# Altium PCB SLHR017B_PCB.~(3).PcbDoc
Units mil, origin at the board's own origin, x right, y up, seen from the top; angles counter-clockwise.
Board outline 3125 x 2100 mil, 2 copper layers (Top Layer, Bottom Layer), stack 61.2 mil thick; 59 components, 16 nets, 85 pads, 115 vias.
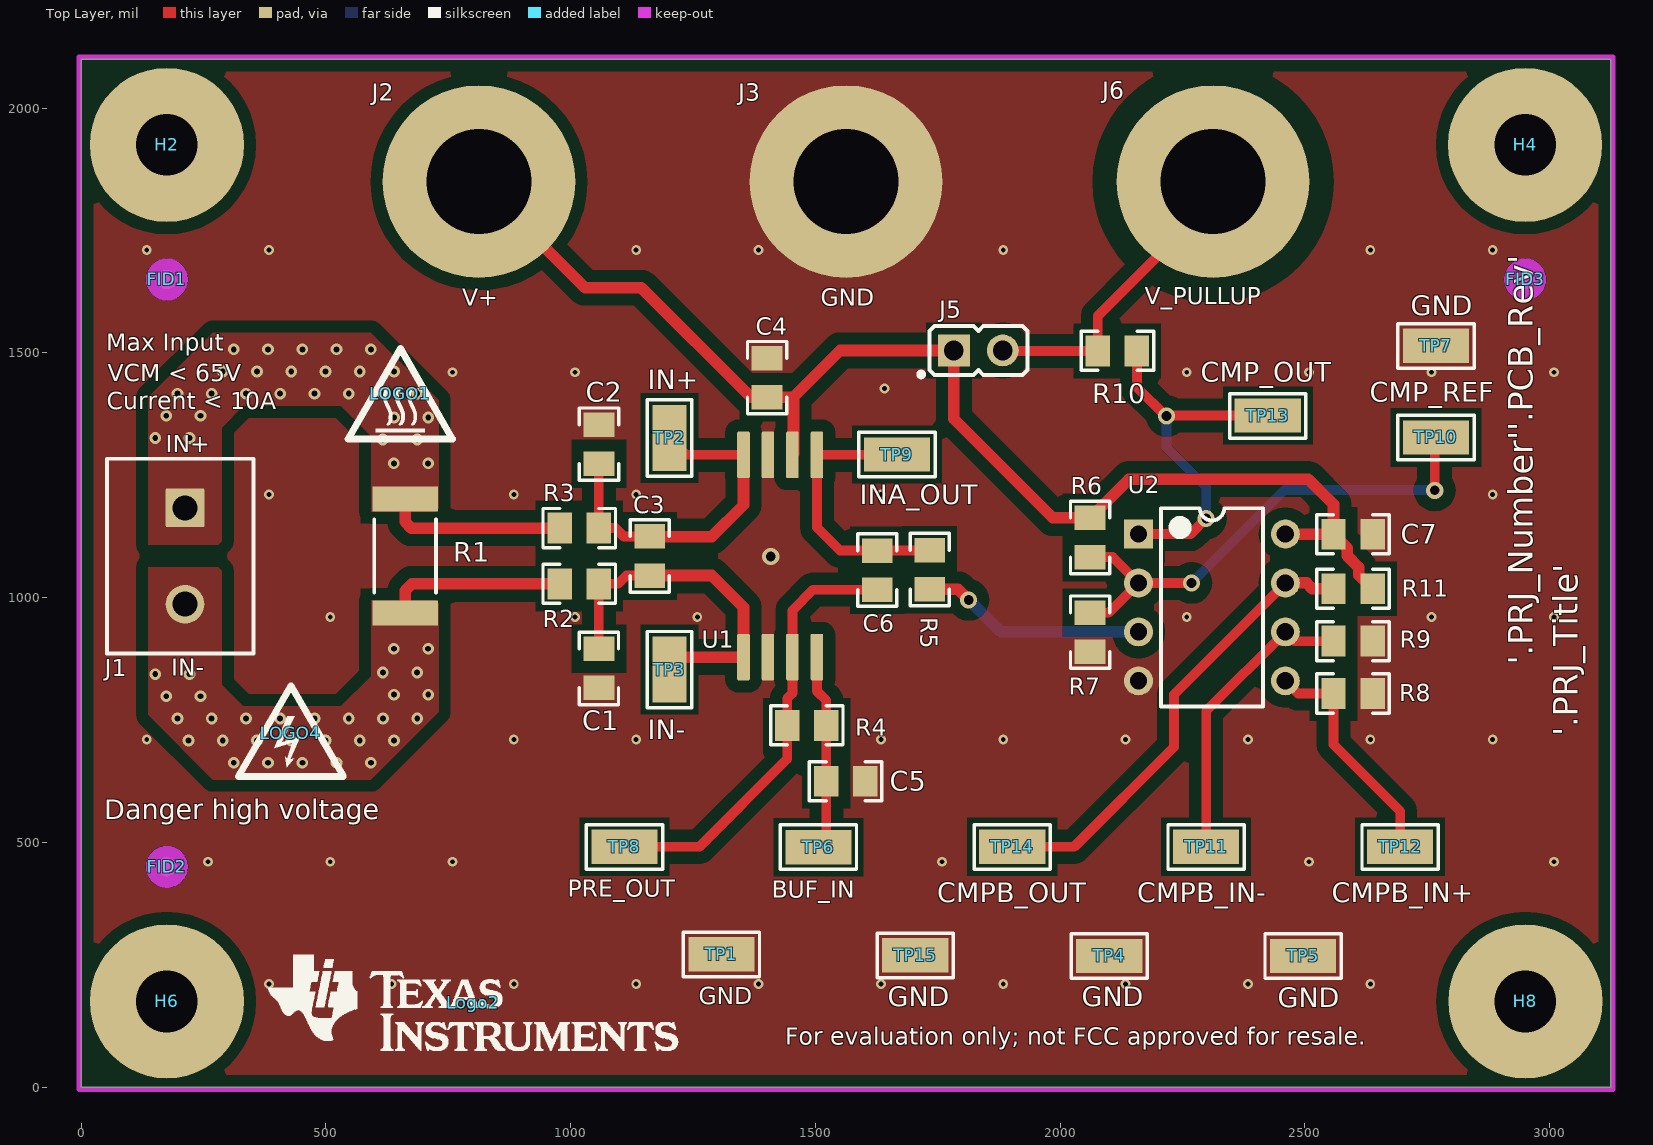
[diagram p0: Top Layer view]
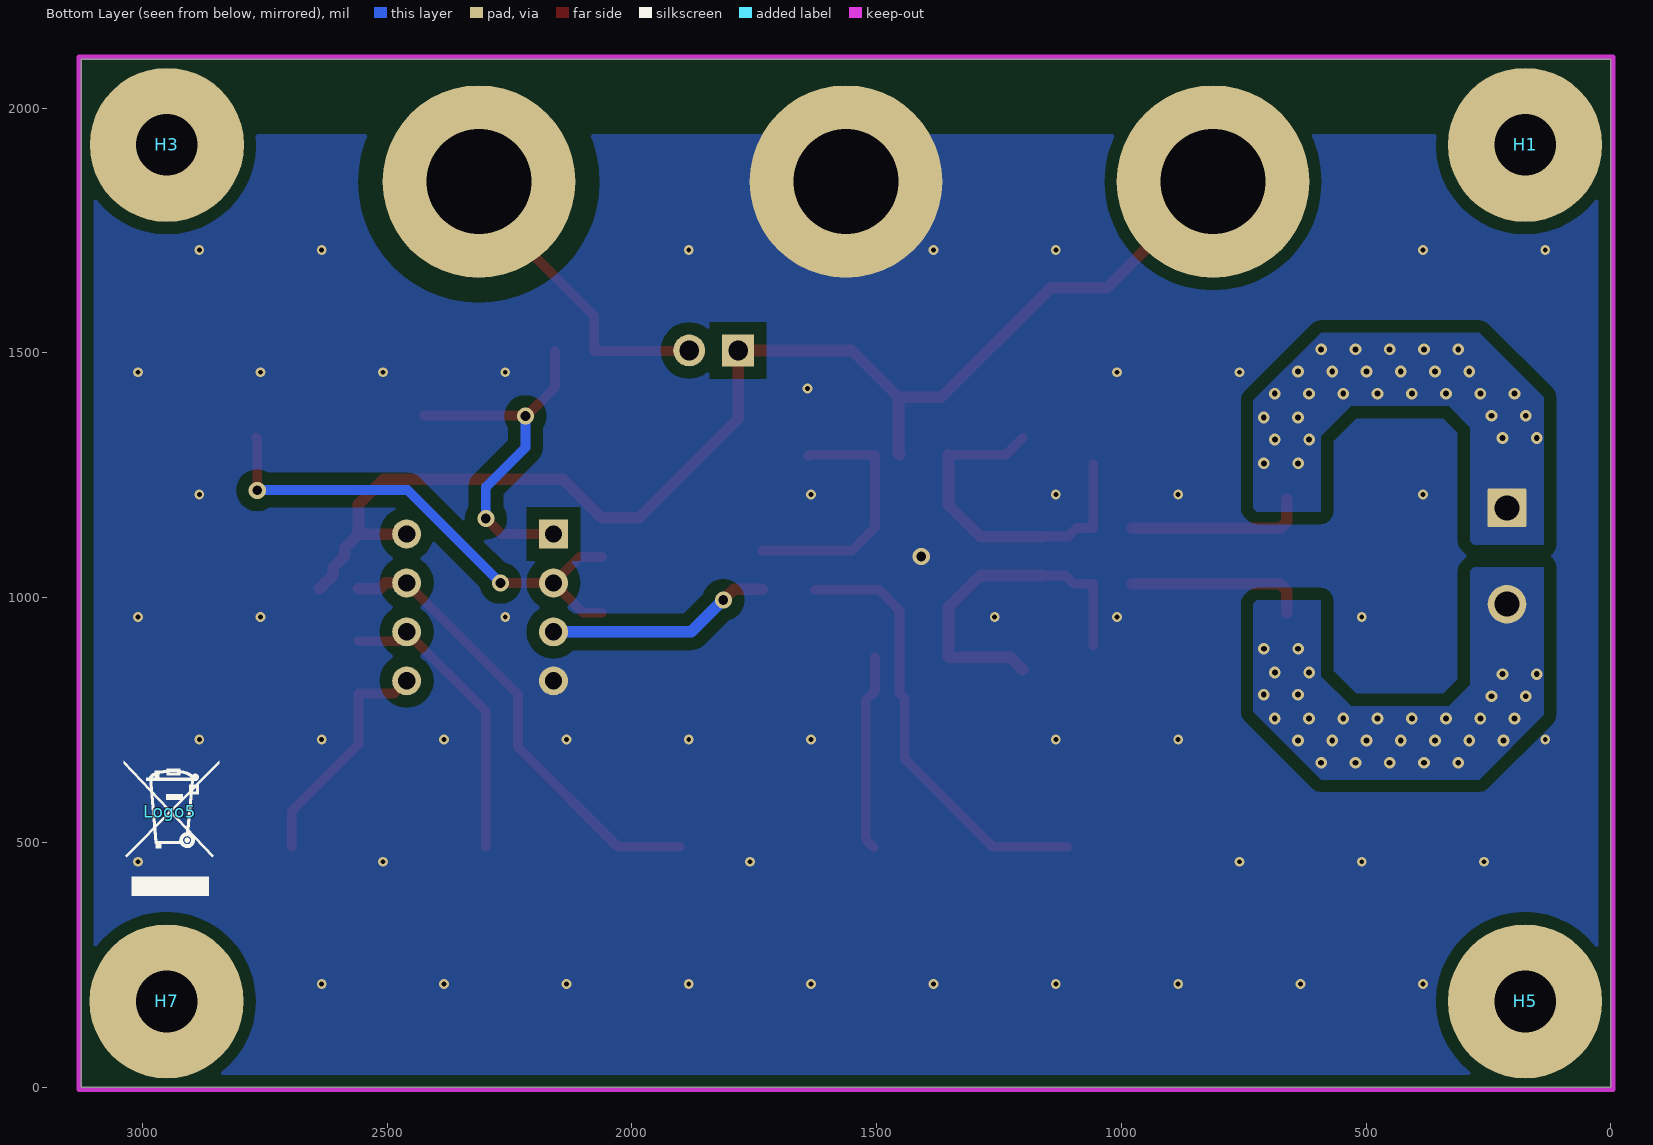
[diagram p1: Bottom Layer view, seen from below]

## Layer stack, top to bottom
Top Solder: solder mask 0.4, Solder Resist, Dk 3.5
Top Layer: signal copper 2.1
Dielectric1: core 57, FR-4 High Tg, Dk 4.8
Bottom Layer: signal copper 2.1
Bottom Solder: solder mask 0.4, Solder Resist, Dk 3.5

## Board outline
0,0 3125,0 3125,2100 0,2100
cut-out: -1616.23,-2039.56 -1606.23,-2039.56 -1606.23,-2029.56 -1616.23,-2029.56

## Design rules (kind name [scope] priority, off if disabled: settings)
AcuteAngle [All] p1: minimum=4.50000000000000E+0001 checktracksonly=FALSE
AssemblyTestPointUsage [All] p1: valid=2
Clearance Clearance_HV [InNetClass('HV_Net')] p1: gap=25 ignorepadtopadclearanceinfootprint=TRUE except(50: THPad-Poly Poly-Poly)
Clearance Clearance_Keepouts [((IsTrack Or IsArc) And Not InPoly) And IsFree and IsKeepOut vs ((IsTrack Or IsArc) And Not InPoly) And IsFree and IsKeepOut] p2: gap=0 ignorepadtopadclearanceinfootprint=FALSE
Clearance Clearance_Fiducial [InComponentClass('FiducialMark')] p3: gap=0 ignorepadtopadclearanceinfootprint=FALSE
Clearance Clearance_BoardEdge_MountingHoles [OnCopper and InComponentClass('Mounting Holes') vs IsKeepOut] p4: gap=40 ignorepadtopadclearanceinfootprint=FALSE except(15: Track-THPad)
Clearance Clearance_BoardEdge_Poly [OnCopper and InPoly vs IsKeepOut] p5: gap=25 ignorepadtopadclearanceinfootprint=FALSE
Clearance Clearance_Jack_Poly [InPolygon vs InPadClass('Jack')] p6: gap=25 ignorepadtopadclearanceinfootprint=FALSE except(50: Arc-Poly Track-Poly SMDPad-Poly THPad-Poly Via-Poly Fill-Poly Poly-Poly)
Clearance Clearance_Poly [InPolygon] p7: gap=25 ignorepadtopadclearanceinfootprint=FALSE
Clearance [All] p8: gap=15 ignorepadtopadclearanceinfootprint=FALSE
ComponentClearance ComponentClearance_MountingHoles_FiducialMarks [InComponentClass('Mounting Holes') vs InComponentClass('FiducialMark')] p1: gap=50 collisioncheckmode=3 verticalgap=10 showdistances=FALSE
ComponentClearance ComponentClearance_Logo [InComponentClass('Logo')] p2: gap=50 collisioncheckmode=3 verticalgap=100000 showdistances=FALSE
ComponentClearance ComponentClearance_ScrewToNut [(HasFootprint('NY PMS 440 0025 PH')) vs (HasFootprint('Keystone_1902C'))] p3: gap=0 collisioncheckmode=3 verticalgap=0 showdistances=FALSE
ComponentClearance ComponentClearance_MountingHoles [InComponentClass('Mounting Holes')] p4: gap=30 collisioncheckmode=3 verticalgap=100000 showdistances=FALSE
ComponentClearance [All] p5: gap=20 collisioncheckmode=3 verticalgap=10 showdistances=FALSE
DiffPairsRouting [All] p1: maxlimit=100 minlimit=10 mostfreqgap=10 toplayer_minwidth=15 toplayer_maxwidth=15 toplayer_prefwidth=15 bottomlayer_minwidth=15 bottomlayer_maxwidth=15 bottomlayer_prefwidth=15 maxuncoupledlength=1000
FabricationTestPointUsage TestPointUsage [All] p1: valid=2 allowmultiple=FALSE
FabricationTestpoint Testpoint [All] p1: side=3 testpointundercomponent=TRUE minsize=40 maxsize=100 preferedsize=60 minholesize=0 maxholesize=40 preferedholesize=32 testpointgrid=1 allowsidetop=TRUE allowsidebottom=TRUE usegrid=TRUE gridtolerance=0.01
FanoutControl Fanout_LCC [IsLCC] p1: bgadir=Out bgaviamode=Centered fanoutstyle=Auto fanoutdirection=Alternating viagrid=1 // Fanout_LCC (Default Rule)
FanoutControl Fanout_BGA [IsBGA] p2: bgadir=Out bgaviamode=Centered fanoutstyle=Auto fanoutdirection=Alternating viagrid=1 // Fanout_BGA (Default Rule)
FanoutControl Fanout_Default [All] p4: bgadir=Out bgaviamode=Centered fanoutstyle=Auto fanoutdirection=Alternating viagrid=1 // Fanout_Default (Default Rule)
FanoutControl Fanout_Small [(CompPinCount < 5)] p5: bgadir=Out bgaviamode=Centered fanoutstyle=Auto fanoutdirection=OutThenIn viagrid=1 // Fanout_Small (Default Rule)
HoleSize [All] p1: absolutevalues=TRUE maxlimit=251 minlimit=8 maxpercent=80.000 minpercent=20.000
MinimumAnnularRing [All] p1: minimumring=6
MinimumSolderMaskSliver MinimumSolderMaskSliver_Logo [InComponentClass('Logo') vs InComponentClass('Logo')] p1: minsoldermaskwidth=0.7
MinimumSolderMaskSliver [All] p2: minsoldermaskwidth=4
PlaneConnect [All] p1: planeconnectstyle=Relief reliefexpansion=10 reliefentries=4 reliefconductorwidth=10 reliefairgap=10
PolygonConnect [All] p1: connectstyle=Direct reliefconductorwidth=30 reliefentries=4 polygonreliefangle="90 Angle" airgapwidth=15
RoutingVias [All] p1: holewidth=12 width=24 viastyle="Through Hole" minholewidth=5 minwidth=5 maxholewidth=20 maxwidth=40
SilkToBoardRegionClearance [Not ((IsComment or IsDesignator) And (Hide <> 'False')) and not InRegion(1000,500,4000,800)] p1:
SilkToSilkClearance SilkToSilkClearance_Pb-FreeLogo [(HasFootprint('Pb-Free_Overlay_Medium') OR HasFootprint('Pb-Free_Overlay_Small')) vs (HasFootprint('Pb-Free_Overlay_Medium') OR HasFootprint('Pb-Free_Overlay_Small'))] p1: silktosilkclearance=0
SilkToSilkClearance [All] p2: silktosilkclearance=4
SilkToSolderMaskClearance SilkToComonentPadClearance [IsPad and InAnycomponent] p1: minsilkscreentomaskgap=5 clearancetoexposedcopper=TRUE
SilkToSolderMaskClearance "Silk to Solder Mask Opening" [All] p2: minsilkscreentomaskgap=4 clearancetoexposedcopper=FALSE
SolderMaskExpansion [All] p1: expansion=0
Width [All] p1: maxlimit=100 minlimit=6 preferedwidth=10 checkconnectedcopper=TRUE
15 further rules are at their usual default settings.

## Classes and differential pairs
component class Header: J5
component class SLHR017B_MainSheet: C1 C2 C3 C4 C5 C6 C7 C? J1 J2 J3 J5 J6 R1 R2 R3 R4 R5 R6 R7 R8 R9 R10 R11 R14 TP1 TP2 TP3 TP4 TP5 TP6 TP7 TP8 TP9 TP10 TP11 TP12 TP13 TP14 TP15 TP? U1 U2 U4
component class AssemblyNote: ZZ1 ZZ2 ZZ3
component class FiducialMark: FID1 FID2 FID3
component class SLHR017B_Hardware: FID1 FID2 FID3 H1 H2 H3 H4 H5 H6 H7 H8 LOGO1 Logo2 Logo3 LOGO4 Logo5 Logo7 ZZ1 ZZ2 ZZ3
component class Logo: Logo2
component class "Mounting Holes": H2 H4 H6 H8
pad class Jack: J4-1 J6-1 J7-1 J8-1

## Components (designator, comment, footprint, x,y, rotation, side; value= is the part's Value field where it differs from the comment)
C1 "C0805C101J1RACTU" 0805_HV 1057.62,855.52 r270 top value=100pF
C2 "C0805C101J1RACTU" 0805_HV 1057.88,1313.51 r270 top value=100pF
C3 "C0805C101J1RACTU" 0805_HV 1161.69,1085 r270 top value=100pF
C4 "C0805C104K1RACTU" 0805_HV 1401.3,1449.33 r90 top value=0.1uF
C5 "VJ0805A150JXACW1BC" 0805_HV 1561.84,624.8 r0 top value=15pF
C6 "C0805C103F1GACTU" 0805_HV 1626.46,1056.19 r90 top value=0.01uF
C7 "C0805C104K1RACTU" 0805_HV 2598.57,1129.42 r0 top value=0.1uF
FID1 "Fiducial" Fiducial10-20 175,1650 r270 top locked
FID2 "Fiducial" Fiducial10-20 175,450 r0 top locked
FID3 "Fiducial" Fiducial10-20 2950,1650 r180 top locked
H1 "1902C" Keystone_1902C 175,1925 r180 bottom locked
H2 "NY PMS 440 0025 PH" "NY PMS 440 0025 PH" 175,1925 r0 top locked
H3 "1902C" Keystone_1902C 2950,1925 r180 bottom locked
H4 "NY PMS 440 0025 PH" "NY PMS 440 0025 PH" 2950,1925 r0 top locked
H5 "1902C" Keystone_1902C 175,175 r180 bottom locked
H6 "NY PMS 440 0025 PH" "NY PMS 440 0025 PH" 175,175 r0 top locked
H7 "1902C" Keystone_1902C 2950.53,175 r180 bottom locked
H8 "NY PMS 440 0025 PH" "NY PMS 440 0025 PH" 2950.53,175 r0 top locked
J1 "691137710002" FP-691137710002_HDR2-MFG 202.17,1085 r270 top
J2 "V+" Keystone_575-4 812.5,1850 r0 top
J3 "GND" Keystone_575-4 1562.5,1850 r0 top
J5 "PBC02SAAN" Sullins_PBC02SAAN 1833.04,1505 r90 top
J6 "VPULLUP" Keystone_575-4 2312.5,1850 r0 top
LOGO1 "CAUTION HOT SURFACE" IEC_HotSurface_Small 651.99,1416.8 r0 top
Logo2 "Texas Instruments" TI_Stacked_Overlay_Small 800.88,172.11 r0 top
Logo3 "FCC disclaimer" FCC_disclaimer 2122.51,-1302.18 r270 top locked
LOGO4 "DANGER HIGH VOLTAGE" IEC_HighVoltage_Small 428.39,722.78 r0 top
Logo5 "WEEE logo" WEEE_Minimum 2942.74,562.77 r180 bottom
R1 "CRA2512-FZ-R025ELF" 2512 661.64,1085 r90 top value=0.025
R2 "ERJ-6GEY0R00V" 0805_HV 1017.48,1028.16 r0 top value=0
R3 "ERJ-6GEY0R00V" 0805_HV 1017.48,1142.08 r0 top value=0
R4 "ERJ-6GEY0R00V" 0805_HV 1482.32,739.05 r180 top value=0
R5 "ERJ-6GEY0R00V" 0805_HV 1733.47,1057.12 r270 top value=0
R6 "ERJ-6GEYJ153V" 0805_HV 2061.21,1122.79 r90 top value=15k
R7 "ERJ-6GEYJ153V" 0805_HV 2061.21,929.33 r90 top value=15k
R8 "RNCP0805FTD10K0" 0805_HV 2598.57,804.08 r180 top value=10.0k
R9 "CRCW080510M0FKEA" 0805_HV 2598.57,911.09 r180 top value=10.0Meg
R10 "ERJ-6GEYJ153V" 0805_HV 2117.02,1504.17 r180 top value=15k
R11 "ERJ-6GEYJ153V" 0805_HV 2598.57,1018.1 r0 top value=15k
TP1 "GND" Testpoint_Keystone_Miniature 1307.8,271.31 r0 top
TP2 "IN+" Testpoint_Keystone_Miniature 1201.64,1326.25 r90 top
TP3 "IN-" Testpoint_Keystone_Miniature 1201.64,852.81 r90 top
TP4 "GND" Testpoint_Keystone_Miniature 2100.32,267.98 r0 top
TP5 "GND" Testpoint_Keystone_Miniature 2496.6,267.98 r0 top
TP6 "BUF_IN" Testpoint_Keystone_Miniature 1505.93,490.01 r180 top
TP7 "GND" Testpoint_Keystone_Miniature 2767.94,1514.57 r0 top
TP8 "PRE_OUT" Testpoint_Keystone_Miniature 1109.68,491.01 r0 top
TP9 "INA_OUT" Testpoint_Keystone_Miniature 1666.48,1292.22 r180 top
TP10 "CMP_REF" Testpoint_Keystone_Miniature 2767.73,1327.31 r0 top
TP11 "CMPB_IN-" Testpoint_Keystone_Miniature 2298.46,491.01 r0 top
TP12 "CMPB_IN+" Testpoint_Keystone_Miniature 2694.74,491.01 r0 top
TP13 "CMP_OUT" Testpoint_Keystone_Miniature 2424.26,1371.97 r0 top
TP14 "CMPB_OUT" Testpoint_Keystone_Miniature 1902.18,491.01 r0 top
TP15 "GND" Testpoint_Keystone_Miniature 1704.05,269.45 r0 top
U1 "INA901HKX/EM" HKX0008A_Custom_B 1428.08,1085.09 r90 top
U2 "LM193AJRLQMLV" NAB0008A 2310.19,979.99 r0 top
ZZ1 "These assemblies are ESD sensitive, ESD precautions shall be observed." AssemblyNote 4602.97,1453.79 r0 top
ZZ2 "These assemblies must be clean and free from flux and all contaminants. Use of no clean flux is not acceptable." AssemblyNote 4602.97,1365.24 r0 top
ZZ3 "These assemblies must comply with workmanship standards IPC-A-610 Class 2, unless otherwise specified." AssemblyNote 4602.97,1276.68 r0 top

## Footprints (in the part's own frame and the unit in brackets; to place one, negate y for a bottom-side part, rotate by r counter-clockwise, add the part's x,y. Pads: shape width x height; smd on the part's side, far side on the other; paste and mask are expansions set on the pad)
0805_HV [mil] "0805 with 30mil clearance between pads"
  rect 50x63 smd: 1(-40,0) 2(40,0)
  silkscreen extent -74,-40 74,40, body extent -43,-29 43,29, height 57
2512 [mm] "Chip Resistor, Body 6.3x3.2mm, IPC Medium Density"
  rect 1.3x3.4 smd: 1(-2.95,0) 2(2.95,0)
  silkscreen extent -1.9,-1.6 1.9,1.6, body extent -3.22,-1.67 3.22,1.67, height 0.71
AssemblyNote [mil] "Assembly Note"
FCC_disclaimer [mil]
Fiducial10-20 [mm]
  round 1 smd mask+0.5: 1(0,0)
  Top Layer keep-out circle w1.178: c0,0 r0.5
FP-691137710002_HDR2-MFG [mm]
  rrect5% 2x2 hole 1.3 paste-1000 mask+0: 1(-2.5,0.25)
  round 2 hole 1.3 paste-1000 mask+0: 2(2.5,0.25)
  silkscreen extent -5.05,-3.8 5.05,3.8, body extent -5.15,-3.9 5.15,3.9, height 0.25
HKX0008A_Custom_B [mm] "CFP, 8-Leads, Body 6.73x6.74mm (max), Pitch 1.27mm, IPC Medium Density"
  rrect15% 2.4x0.65 smd: 1(-5.25,1.905) 2(-5.25,0.635) 3(-5.25,-0.635) 4(-5.25,-1.905) 5(5.25,-1.905) 6(5.25,-0.635) 7(5.25,0.635) 8(5.25,1.905)
  body extent -3.25,-3.24 3.25,3.24, height 2.51
IEC_HighVoltage_Small [mil]
  silkscreen extent -107,-88 107,97
IEC_HotSurface_Small [mil]
  silkscreen extent -107,-93 107,92
Keystone_575-4 [mm] "Banana Jack"
  round 10 hole 5.45: 1(0,0)
  body extent -3.95,-3.95 3.92,3.93, height 2.36
Keystone_1902C [mil] "Hex Standoff, 4-40 threaded, nylon"
  round 1 on Mech4: 0(0,0)
  body extent -145,-126 146,126, height 501
NAB0008A [mm] "DIP, 8-Leads, Row Spacing 7.62mm, Pitch 2.54mm, Body 9.78x6.73mm"
  rect 1.5x1.5 hole 0.9: 1(-3.81,3.81)
  round 1.5 hole 0.9: 2(-3.81,1.27) 3(-3.81,-1.27) 4(-3.81,-3.81) 5(3.81,-3.81) 6(3.81,-1.27) 7(3.81,1.27) 8(3.81,3.81)
  silkscreen extent -2.65,-5.15 2.65,5.15, body extent -3.91,-5.08 3.96,5.08, height 5.17
"NY PMS 440 0025 PH" [mm] "4-40 nylon screw and mounting hole"
  round 8 hole 3.2: 1(0,0)
  body extent -3.3,-3.3 3.3,3.3, height 2.69
Sullins_PBC02SAAN [mm] "Sullins 100mil, 1x2, 230 mil above insulator"
  rect 1.65x1.65 hole 1.016: 1(0,1.27)
  round 1.65 hole 1.016: 2(0,-1.27)
  silkscreen extent -1.37,-2.54 1.27,3.1, body extent -1.27,-2.54 1.27,2.54, height 8.38
Testpoint_Keystone_Miniature [mil] "Miniature SMT test point"
  rect 135x70 smd: 1(0,0)
  silkscreen extent -78,-46 78,45, body extent -52,-20 52,20, height 61
TI_Stacked_Overlay_Small [mil]
  silkscreen extent -418,-98 418,98
WEEE_Minimum [mil] "WEEElie bin"
  silkscreen extent -95,-172 99,104

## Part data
C1 C2 C3: library part CMP-0007706-2, "CAP, CERM, 100 pF, 100 V, +/- 5%, X7R, 0805", Cap_Case=0805, Manufacturer=Kemet, Supplier Part Number 1=80-C0805C101J1R, TempCo=X7R, Tolerance_%=5%, Value1=Unknown, Value2=100V, ValueDisplayed=100pF
C4 C7: library part CMP-0007722-2, "CAP, CERM, 0.1 uF, 100 V, +/- 10%, X7R, 0805", Cap_Case=0805, Manufacturer=Kemet, Supplier Part Number 1=399-3486-1-ND, TempCo=X7R, Tolerance_%=10%, Value1="0.064 ohm", Value2=100V, ValueDisplayed=0.1uF
C5: library part CMP-0008431-2, "CAP, CERM, 15 pF, 50 V, +/- 5%, C0G/NP0, 0805", Cap_Case=0805, Manufacturer=Vishay-Bccomponents, Supplier Part Number 1=BC1258CT-ND, TempCo=C0G/NP0, Tolerance_%=5%, Value1=Unknown, Value2=50V, ValueDisplayed=15pF
C6: library part CMP-0007716-2, "CAP, CERM, 0.01 uF, 100 V, +/- 1%, C0G/NP0, 0805", Cap_Case=0805, Manufacturer=Kemet, Supplier Part Number 1=399-11160-1-ND, TempCo=C0G/NP0, Tolerance_%=1%, Value1=Unknown, Value2=100V, ValueDisplayed=0.01uF
FID1 FID2 FID3: library part CMP-0077181-1, "Fiducial mark.  There is nothing to buy or mount.", Manufacturer=N/A
H1 H3 H5 H7: library part CMP-0003610-1, "Standoff, Hex, 0.5\"L #4-40 Nylon", Manufacturer=Keystone, Supplier Part Number 1=36-1902C-ND
H2 H4 H6 H8: library part CMP-0003617-1, "Machine Screw, Round, #4-40 x 1/4, Nylon, Philips panhead", Manufacturer="B&F Fastener Supply", Supplier Part Number 1=H542-ND
J1: library part CMP-0087503-1, "TERM BLK 2POS SIDE ENTRY 5MM PCB", Current_A=16A, Manufacturer="Würth Elektronik", Voltage_V=300V
J2 J3 J6: library part CMP-0055165-2, "Standard Banana Jack, Uninsulated, 5.5mm", Manufacturer=Keystone, PartNumber=575-4, Supplier Part Number 1=36-575-4-ND
J5: library part CMP-0054566-1, "Header, 100mil, 2x1, Gold, TH", Color=Black, Current_A=3A, Manufacturer="Sullins Connector Solutions", Supplier Part Number 1=S1011E-02-ND, Voltage_V=1.8kV
LOGO1: library part CMP-0074837-1, "IEC 61010-1 Hot Surface Warning"
Logo2: library part CMP-0074838-1, "Texas Instrument Corporate Signature"
Logo3: library part CMP-0074847-1, "FCC_disclaimer"
LOGO4: library part CMP-0074835-1, "IEC 61010-1 High Voltage Warning"
Logo5: library part CMP-0074769-1
R1: library part CMP-0015421-2, "RES, 0.025, 1%, 3 W, 2512", Manufacturer=Bourns, Power_W=3W, Supplier Part Number 1=652-CRA2512FZR025ELF, TempCo="75 ppm/C", Tolerance_%=1%, Value_Code=R025, ValueDisplayed=0.025
R2 R3 R4 R5: library part CMP-0020616-3, "RES, 0, 5%, 0.125 W, AEC-Q200 Grade 0, 0805", Manufacturer=Panasonic, Power_W=125mW, Supplier Part Number 1=P0.0ACT-ND, TempCo="600 ppm/C", Tolerance_%=5%, Value2=0.125W, Value_Code=0000, ValueDisplayed=0
R6 R7 R10 R11: library part CMP-0020646-3, "RES, 15 k, 5%, 0.125 W, AEC-Q200 Grade 0, 0805", Manufacturer=Panasonic, Power_W=125mW, Supplier Part Number 1=P15KACT-ND, TempCo="200 ppm/C", Tolerance_%=5%, Value2=0.125W, Value_Code=15k0, ValueDisplayed=15k
R8: library part CMP-0084247-1, "RES, 10.0 k, 1%, 0.25 W, AEC-Q200 Grade 0, 0805", Manufacturer="Stackpole Electronics Inc", Power_W=250mW, TempCo="100 ppm/C", Tolerance_%=1%, Value2=0.25W, Value_Code=10k0, ValueDisplayed=10.0k
R9: library part CMP-0020846-3, "RES, 10.0 M, 1%, 0.125 W, AEC-Q200 Grade 0, 0805", Manufacturer=Vishay-Dale, Power_W=125mW, Supplier Part Number 1=541-10.0MCCT-ND, TempCo="100 ppm/C", Tolerance_%=1%, Value2=0.125W, Value_Code=10M0, ValueDisplayed=10.0M
TP1 TP2 TP3 TP4 TP5 TP6 TP7 TP8 TP9 TP10 TP11 TP12 TP13 TP14 TP15: library part CMP-0055152-1, "Test Point, Miniature, SMT", Manufacturer=Keystone, PartNumber=5015, Supplier Part Number 1=36-5015TR-ND
U1: library part CMP-0081563-2, "Voltage Output, Unidirectional Measurement Current-Shunt Monitor, HKX0008A (CFP-8)", Alternate Manufacturer="Texas Instruments", Rating=Space
U2: library part CMP-0067897-1, "Low Power Low Offset Voltage Dual Comparator, 8-pin CerDIP", Manufacturer="Texas Instruments", Package Reference=NAB0008A, PackageTopMarking="NSZSSXXYYA*LM193AJRLV Q*5962R*9452603VPA", PowerWise=N
ZZ1: library part CMP-0077236-1
ZZ2: library part CMP-0077237-1
ZZ3: library part CMP-0077238-1

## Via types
v1: diameter 24, hole 12, Top Layer to Bottom Layer, tented both sides, 59 vias
v2: diameter 20, hole 10, Top Layer to Bottom Layer, tented both sides, 50 vias
v3: diameter 35, hole 20, Top Layer to Bottom Layer, tented both sides, 6 vias

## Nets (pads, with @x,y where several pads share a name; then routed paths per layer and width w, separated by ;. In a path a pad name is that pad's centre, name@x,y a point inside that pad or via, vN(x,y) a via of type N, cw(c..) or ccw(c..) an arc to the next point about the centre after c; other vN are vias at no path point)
GND: C1.2 C2.1 C4.2 C5.2 C7.2 J3.1 R7.1 R8.1 R9.1 TP1.1 TP4.1 TP5.1 TP7.1 TP15.1 U1.2 U1.7 U2.4
  other v2: 383.77,210.44 633.77,210.44 883.77,210.44 1133.77,210.44 1383.77,210.44 1633.77,210.44 1883.77,210.44 2133.77,210.44 2383.77,210.44 2633.77,210.44 258.77,460.44 508.77,460.44 758.77,460.44 1758.77,460.44 2508.77,460.44 3008.77,460.44 133.77,710.44 883.77,710.44 1133.77,710.44 1633.77,710.44 1883.77,710.44 2133.77,710.44 2383.77,710.44 2633.77,710.44 2883.77,710.44 508.77,960.44 1008.77,960.44 1258.77,960.44 2258.77,960.44 2758.77,960.44 3008.77,960.44 383.77,1210.44 883.77,1210.44 1133.77,1210.44 1633.77,1210.44 2883.77,1210.44 1640.94,1427.27 758.77,1460.44 1008.77,1460.44 2258.77,1460.44 2508.77,1460.44 2758.77,1460.44 3008.77,1460.44 133.77,1710.44 383.77,1710.44 1133.77,1710.44 1383.77,1710.44 1883.77,1710.44 2633.77,1710.44 2883.77,1710.44
  other v3: 1408.83,1084.2
NetC1_1: C1.1 C3.2 R2.2 TP3.1 U1.1 | length 720.3
  Top Layer w20: C1.1@1057.49,901.51 R2.2 1096.94,1028.16 1113.94,1045.16 C3.2@1161.69,1045.16
  Top Layer w23.62: C3.2@1161.69,1045.16 1288.5,1045.16 1353.08,980.58 U1.1 1227.23,878.4 TP3.1
NetC2_2: C2.2 C3.1 R3.2 TP2.1 U1.8 | length 727.5
  Top Layer w20: C2.2@1057.49,1272.25 R3.2 1091.3,1142.08 1108.38,1125 C3.1 ; TP2.1 1236.11,1291.78 U1.8
  Top Layer w23.62: C3.1@1161.69,1124.84 1288.5,1124.84 1353.08,1189.42 U1.8@1353.08,1291.6
NetC5_1: C5.1 R4.1 TP6.1 U1.4 | length 403.2
  Top Layer w20: U1.4 1503.08,808.79 1522.32,789.55 R4.1 1522.32,506.4 TP6.1
NetC6_1: C6.1 R4.2 TP8.1 U1.3 | length 906
  Top Layer w20: TP8.1 1263.24,491.01 1442.32,670.09 R4.2 1442.32,794.08 1453.08,804.84 U1.3 1453.08,973.95 1495.32,1016.19 C6.1
NetC6_2: C6.2 R5.1 TP9.1 U1.5 | length 535.6
  Top Layer w20: TP9.1@1639.89,1289.54 1637.65,1291.78 U1.5 1503.08,1143.53 1550.42,1096.19 C6.2 R5.1@1733.1,1096.19
NetJ1_1: J1.1 R1.2 R3.1 | length 367.5
  Top Layer w23.62: R1.2 661.64,1154.74 674.3,1142.08 R3.1
  other v1: 638.73,1274.37 708.73,1274.37 616.25,1322.95 686.25,1322.95 151.14,1326.29 221.14,1326.29 638.89,1368.19 708.89,1368.19 173.77,1371.53 243.77,1371.53 196.41,1416.76 266.41,1416.76 336.41,1416.76 406.41,1416.76 476.41,1416.76 546.41,1416.76 616.41,1416.76 686.41,1416.76 289.05,1462 359.05,1462 429.05,1462 499.05,1462 569.05,1462 639.05,1462 311.68,1507.24 381.68,1507.24 451.68,1507.24 521.68,1507.24 591.68,1507.24
NetJ1_2: J1.2 R1.1 R2.1 | length 366.9
  Top Layer w23.62: R1.1 661.64,1014.02 675.78,1028.16 R2.1
  other v1: 311.68,662.76 381.68,662.76 451.68,662.76 521.68,662.76 591.68,662.76 219.05,708 289.05,708 359.05,708 429.05,708 499.05,708 569.05,708 639.05,708 196.41,753.24 266.41,753.24 336.41,753.24 406.41,753.24 476.41,753.24 546.41,753.24 616.41,753.24 686.41,753.24 173.77,798.47 243.77,798.47 638.89,801.81 708.89,801.81 151.14,843.71 221.14,843.71 616.25,847.05 686.25,847.05 638.73,895.63 708.73,895.63
NetJ5_2: J5.2 J6.1 R10.2 | length 637.7
  Top Layer w20: J5.2 1883.87,1504.17 R10.2 2077.02,1575.89 2312.5,1811.37 J6.1
NetR5_2: R5.2 U2.3 | length 462.8
  Top Layer w23.62: R5.2 1791.37,1017.12 v3(1813.1,995.39)
  Bottom Layer w23.62: v3(1813.1,995.39) 1878.5,929.99 U2.3
NetR6_1: R6.1 R7.2 TP10.1 U2.2 | length 1037.4
  Top Layer w20: R7.2 2099.52,969.33 U2.2 ; R6.1 2107.39,1082.79 U2.2 ; v3@2266.53,1030.62 2265.9,1029.99 U2.2 ; v3(2765.28,1219.27) 2765.28,1324.86 TP10.1
  Bottom Layer w20: v3(2268.64,1030.02) 2458.63,1220.01 v3@2766.77,1220.01
NetR8_2: R8.2 TP12.1 U2.5 | length 478.6
  Top Layer w20: U2.5 2486.1,804.08 R8.2 2558.57,699.84 2694.74,563.66 TP12.1
NetR9_2: R9.2 TP11.1 U2.6 | length 612.2
  Top Layer w20: TP11.1 2298.46,768.27 U2.6 2479.09,911.09 R9.2
NetR10_1: R10.1 TP13.1 U2.1 | length 759.9
  Top Layer w20: R10.1 2157.02,1429.76 2214.81,1371.97 TP13.1 ; U2.1 2266.86,1129.99 v3(2298.34,1161.48)
  Bottom Layer w20: v3(2217.42,1371.1) 2217.42,1306.88 2298.34,1225.96 v3(2298.34,1161.48)
NetR11_1: R11.1 TP14.1 U2.7 | length 947.6
  Top Layer w20: TP14.1 2028.83,491.01 2232.4,694.58 2232.4,802.21 U2.7
  Top Layer w23.62: U2.7 2503.47,1029.99 2515.36,1018.1 R11.1
V+: C4.1 C7.1 J2.1 J5.1 R6.2 R11.2 U1.6 U2.8 | length 2668.9
  Top Layer w23.62: J2.1 1029.35,1633.15 1144.25,1633.15 1367.62,1409.78 1455.18,1409.78 ; U1.6 1455.18,1293.88 1455.18,1409.78 ; U2.8 2460.76,1129.42 C7.1 ; R11.2 2610.38,1046.29 2610.38,1061.64 2586.75,1085.26 2586.75,1101.23 C7.1 ; 1455.18,1409.78 1550.4,1505 J5.1 1783.04,1365.07 1985.32,1162.79 R6.2 2140.63,1242.21 2506.92,1242.21 2558.57,1190.56 C7.1
pads on no net: FID1.1 FID2.1 FID3.1 H1.0 H2.1 H3.0 H4.1 H5.0 H6.1 H7.0 H8.1

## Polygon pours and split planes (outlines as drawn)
NetJ1_2 on Bottom Layer "NETJ1_2_L02_P290" (solid, remove dead copper, pour order 290): 136.92,1062.1 286.81,1062.23 286.81,822.43 331.21,778.02 530.27,777.93 592.33,839.87 592.38,994.28 729.96,994.63 729.96,766.5 591.85,628.39 268.96,628.39 136.92,760.43
NetJ1_1 on Bottom Layer "NETJ1_1_L02_P292" (solid, remove dead copper, pour order 292): 136.92,1107.9 286.81,1107.77 286.81,1347.57 331.21,1391.98 530.27,1392.07 592.33,1330.13 592.38,1175.72 729.96,1175.37 729.96,1403.5 591.85,1541.61 268.96,1541.61 136.92,1409.57
GND on Bottom Layer "GND" (solid, remove dead copper, pour order 298): -12.43,-152.81 3112.41,-152.81 3112.41,1947.2 3112.38,1947.23 -12.39,1947.23 -12.51,1947.12
GND on Top Layer "GND_L01_P300" (solid, remove dead copper, pour order 300): -4.36,2106.37 -4.29,2106.3 3120.53,2106.3 3120.53,6.3 -4.47,6.3
NetJ1_2 on Top Layer "NETJ1_2_L01_P294" (solid, remove dead copper, pour order 294): 136.92,1062.1 286.81,1062.23 286.81,822.43 331.21,778.02 530.27,777.93 592.33,839.87 592.38,994.28 729.96,994.63 729.96,766.5 591.85,628.39 268.96,628.39 136.92,760.43
NetJ1_1 on Top Layer "NETJ1_1_L01_P288" (solid, remove dead copper, pour order 288): 136.92,1107.9 286.81,1107.77 286.81,1347.57 331.21,1391.98 530.27,1392.07 592.33,1330.13 592.38,1175.72 729.96,1175.37 729.96,1403.5 591.85,1541.61 268.96,1541.61 136.92,1409.57

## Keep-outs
Keep-Out Layer:
  lines w10: -5,-5 3130,-5 3130,2105 -5,2105 -5,-5
  text ".Layer_Name" at -347.23,-1364.06 h60

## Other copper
Top Layer:
  text ".Layer_Name" at -347.23,-1364.06 h60
Bottom Layer:
  text ".Layer_Name" at -347.23,-1364.06 h60

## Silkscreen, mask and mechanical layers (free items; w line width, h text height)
Top Overlay:
  text "V_PULLUP" at 2173.36,1599.44 h35
  text "V+" at 778.33,1596.53 h35
  text "GND" at 1510.83,1596.53 h35
  text "Max Input" at 51.3,1504.92 h35
  text "VCM < 65V" at 53.66,1441.87 h35
  text "Current < 10A" at 52.01,1384.68 h35
  text "IN+" at 172.43,1297.43 h35
  text "'.PRJ_Number''.PCB_Rev'" at 2965.63,862.56 h50 r90
  text "IN-" at 183.7,839.98 h35
  text "'.PRJ_Title'" at 3057.89,716.77 h50 r90
  text "Danger high voltage" at 47.08,547.31 h40
  text ".Layer_Name" at -347.23,-1364.06 h60
Bottom Overlay:
  text ".Layer_Name" at -347.23,-1364.06 h60
Top Paste:
  text ".Layer_Name" at -347.23,-1364.06 h60
Bottom Paste:
  text ".Layer_Name" at -347.23,-1364.06 h60
Top Solder:
  text ".Layer_Name" at -347.23,-1364.06 h60
  text ".Layer_Name" at -347.23,-1364.06 h60
Bottom Solder:
  text ".Layer_Name" at -347.23,-1364.06 h60
Drill Guide:
  text ".Layer_Name" at -347.23,-1364.06 h60
M1 Board Outline:
  the board outline again, w10
  text ".Layer_Name" at -347.23,-1364.06 h60
M2 Board Dimensions:
  rectangle: -799.23,-905.56 -424.23,-780.56
  rectangle: -924.23,-780.56 -799.23,-655.56
  lines w7: -924.23,-780.56 75.77,-780.56 ; -799.23,-905.56 -799.23,-655.56 ; -674.23,-905.56 -674.23,-655.56 ; -424.23,-905.56 -424.23,-655.56 ; -174.23,-905.56 -174.23,-655.56 ; -924.23,-905.56 -924.23,-655.56 75.77,-655.56 75.77,-905.56 -924.23,-905.56
  text ".Layer_Name" at -347.23,-1364.06 h60
M3 3D STEP Top:
  text ".Layer_Name" at -347.23,-1364.06 h60
M4 3D STEP Bottom:
  text ".Layer_Name" at -347.23,-1364.06 h60
M5 Assembly Top:
  lines w10: -1216.23,-1435.73 5383.77,-1435.73 ; -1216.23,-1232.4 5385.77,-1232.4 ; -1216.23,-1029.06 -1216.23,-1639.06 2788.77,-1639.06 5385.77,-1639.06 5385.77,-1029.06 -1215.73,-1029.06 -1215.73,-1639.06 359.77,-1639.06 ; 1248.77,-1639.06 1248.77,-1029.06 ; 2515.77,-1232.4 2515.77,-1029.06 ; 3355.77,-1232.4 3355.77,-1029.06 ; 3977.77,-1645.56 3977.77,-1442.73
  text "COMPONENTS MARKED 'DNP' SHOULD NOT BE POPULATED." at 229.27,-824.06 h60
  text "ASSEMBLY VARIANT:" at 228.77,-939.56 h60
  text ".VariantName" at 1264.77,-939.56 h60
  text "PCB VIEWED FROM TOP SIDE" at -1152.73,-1161.23 h60
  text "BOARD #:" at 1323.77,-1161.23 h60
  text ".PRJ_Number" at 1869.27,-1161.23 h60
  text "REV:" at 2713.77,-1161.23 h60
  text ".PCB_Rev" at 3005.27,-1161.23 h60
  text "SVN REV:" at 3551.77,-1161.23 h60
  text ".VersionControl_RevNumber" at 4057.77,-1161.23 h60
  text "TID #:" at 1323.77,-1364.56 h60
  text ".TID" at 1869.27,-1364.56 h60
  text "PLOT NAME =" at -1152.73,-1569.9 h60
  text ".plot_File_Name" at -347.23,-1569.9 h60
  text "GENERATED    :" at 1325.77,-1569.9 h60
  text ".Print_Date" at 2195.27,-1569.9 h60
  text ".Print_Time" at 2924.27,-1569.9 h60
  text "TEXAS INSTRUMENTS" at 4188.77,-1569.9 h60
M6 Assembly Bottom:
  lines w10: -1216.73,-1232.9 5385.27,-1232.9 ; -1214.73,-1436.23 5385.27,-1436.23 ; 191.27,-1646.06 191.27,-1443.23 ; 813.27,-1232.9 813.27,-1029.56 ; 1653.27,-1232.9 1653.27,-1029.56 ; 2920.27,-1639.56 2920.27,-1029.56 ; 3809.27,-1639.56 5384.77,-1639.56 5384.77,-1029.56 -1216.73,-1029.56 -1216.73,-1639.56 1380.27,-1639.56 5385.27,-1639.56 5385.27,-1029.56
  text "COMPONENTS MARKED 'DNP' SHOULD NOT BE POPULATED." at 5177.77,-823.56 h60
  text ".VariantName" at 4133.77,-939.56 h60
  text "ASSEMBLY VARIANT:" at 5172.77,-939.56 h60
  text ".VersionControl_RevNumber" at 111.27,-1161.73 h60
  text "SVN REV:" at 617.27,-1161.73 h60
  text ".PCB_Rev" at 1163.77,-1161.73 h60
  text "REV:" at 1455.27,-1161.73 h60
  text ".PRJ_Number" at 2299.77,-1161.73 h60
  text "BOARD #:" at 2845.27,-1161.73 h60
  text "PCB VIEWED FROM BOTTOM SIDE" at 5321.77,-1161.73 h60
  text ".TID" at 2299.77,-1365.06 h60
  text "TID #:" at 2845.27,-1365.06 h60
  text "TEXAS INSTRUMENTS" at -19.73,-1570.4 h60
  text ".Print_Time" at 1244.77,-1570.4 h60
  text ".Print_Date" at 1973.77,-1570.4 h60
  text "GENERATED    :" at 2843.27,-1570.4 h60
  text ".plot_File_Name" at 4516.27,-1570.4 h60
  text "PLOT NAME =" at 5321.77,-1570.4 h60
M7 LPKF Text Top:
  text ".Layer_Name" at -347.23,-1364.06 h60
M8 LPKF Text Bottom:
  text ".Layer_Name" at -347.23,-1364.06 h60
M9 Title Sheet:
  drawing of 57 lines, arcs and shapes, not listed
  text "1" at -184.39,7530.94 h70
  text "2" at 2311.27,7530.94 h70
  text "3" at 4800.61,7530.94 h70
  text "4" at 7307.28,7530.94 h70
  text "5" at 9806.27,7530.94 h70
  text "6" at 12311.27,7530.94 h70
  text "A" at -1340.73,6387.94 h70
  text "A" at 13459.27,6387.94 h70
  text "B" at -1340.73,4007.94 h70
  text "B" at 13459.27,4007.94 h70
  text "C" at -1340.73,1632.94 h70
  text "C" at 13459.27,1632.94 h70
  text "PROJECT TITLE:" at 10419.27,-228.06 h45
  text ".PRJ_Title" at 10469.27,-361.39 h70
  text "DESIGNED FOR:" at 10419.27,-529.06 h45
  text ".PRJ_Customer" at 10469.27,-669.06 h70
  text "D" at -1340.73,-737.06 h70
  text "D" at 13459.27,-737.06 h70
  text "FILE NAME:" at 10419.27,-829.06 h45
  text ".PCB_File_Name_No_Path" at 10469.27,-949.06 h70
  text "Texas Instruments (TI) and/or its licensors do not warrant the accuracy or completeness of this specification" at 5449.77,-1110.9 h45
  text "ENGINEER:" at 10419.27,-1119.06 h45
  text "LAYOUT BY:" at 11924.27,-1119.06 h45
  text "or any information contained therein. TI and/or its licensors do not warrant that this design will meet" at 5404.79,-1223.57 h45
  text ".PRJ_Engineer" at 10469.27,-1274.05 h70
  text ".PCB_Layout" at 11974.77,-1274.05 h70
  text "the specifications, will be suitable for your application or fit for any particular purpose, or will operate in" at 5404.79,-1336.23 h45
  text ".Layer_Name" at -347.23,-1364.06 h60
  text "ALTIUM DESIGNER VERSION:" at 11924.27,-1429.06 h45
  text "an implementation. TI and/or its licensors do not warrant that the design is production worthy. You should" at 5404.79,-1448.9 h45
  text "completely validate and test your design implementation to confirm the system functionality for your application." at 5449.77,-1561.56 h45
  text ".print_Scale" at 10469.27,-1562.39 h70
  text ".Application_BuildNumber" at 11974.77,-1562.39 h70
  text "1" at -184.39,-1769.06 h70
  text "2" at 2311.27,-1769.06 h70
  text "3" at 4800.61,-1769.06 h70
  text "4" at 7307.28,-1769.06 h70
  text "5" at 9806.27,-1769.06 h70
  text "6" at 11663.98,-1774.87 h70
  text "WO#307451-7449-D" at 12063.89,-1777.37 h70
M10 Fab Notes:
  drawing of 189 lines, arcs and shapes, not listed
  text "DESIGN INFORMATION" at 11471.29,5850.61 h60
  text "20" at 11881.72,5719.28 h60
  text "MIN. TRACK WIDTH:" at 10826.73,5718.49 h60
  text "MIL" at 12077.73,5718.49 h60
  text "MIN. CLEARANCE:" at 10826.73,5594.36 h60
  text "MIL" at 12077.73,5594.36 h60
  text "19.7" at 11836.15,5591.95 h60
  text "24" at 11862.7,5478.69 h60
  text "MIN. VIA PAD SIZE:" at 10826.73,5470.23 h60
  text "MIL" at 12077.73,5470.23 h60
  text "0.05mm (2MIL)" at 11521.73,5340.33 h60
  text "MINIMUM ANNULAR RING" at 10497.5,5332.11 h60
  text "EXTERNAL" at 12229.73,5332.11 h60
  text "PER" at 10697.5,5221.99 h60
  text "IPC-D-275 CLASS 2 LEVEL C" at 10917.5,5221.98 h60
  text "MIL, HOLES" at 12405.73,5121.51 h60
  text "+/-" at 12013.27,5112.92 h60
  text "+/-" at 12867.27,5112.92 h60
  text "REGISTRATION TOLERANCES:" at 10497.5,5111.86 h60
  text "METAL" at 11697.27,5111.86 h60
  text "5" at 12273.47,5111.86 h60
  text "3" at 13106.47,5111.86 h60
  text "MIL" at 13222.73,5111.86 h60
  text "HOLE SIZE TOLERANCE (UNLESS OTHERWISE SPECIFIED):" at 10497.5,5013.54 h60
  text "+/-" at 12867.27,5010.67 h60
  text "3" at 13106.47,5009.61 h60
  text "MIL" at 13222.73,5009.6 h60
  text "MATERIAL:" at 10422.73,4871.96 h60
  text "FR-4 High Tg" at 11409.17,4743.43 h60
  text "FR-408" at 10843.73,4730.93 h60
  text "OTHER" at 12331.73,4730.93 h60
  text "X" at 11260.86,4729.44 h60
  text "62 MIL (1.6mm) +/-10%" at 11163.83,4587.9 h60
  text "X" at 11043.74,4585.44 h60
  text "THICKNESS:" at 10497.5,4579.68 h60
  text "OTHER" at 12448.73,4579.68 h60
  text "TOLERANCE:" at 10497.5,4441.36 h60
  text "X" at 11345.74,4441.36 h60
  text "ANSI IPC-6012 TYPE 3 CLASS 2" at 11523.75,4441.36 h60
  text "OTHER +/-" at 11523.73,4297.17 h60
  text "BOW & TWIST:" at 10497.5,4151.98 h60
  text "X" at 11345.74,4151.98 h60
  text "ANSI IPC-6012 TYPE 3 CLASS 2" at 11523.75,4151.98 h60
  text "OTHER +/-" at 11523.73,4005.29 h60
  text "DRILLING:" at 10422.73,3874.67 h60
  text "NC_DRILL FILES" at 12183.73,3769.48 h60
  text "REFERENCE:" at 10497.5,3765.54 h60
  text "X" at 11154.74,3765.44 h60
  text "AS SHOWN" at 11332.73,3765.54 h60
  text "X" at 12055.74,3765.54 h60
  text "OTHER" at 12481.73,3623.29 h60
  text "PTH COPPER THICKNESS:" at 10497.18,3619.76 h60
  text "X" at 11636.41,3619.76 h60
  text "20-30 um" at 11764.41,3619.76 h60
  text "BOARD FINISH:" at 10422.73,3472.16 h60
  text "SILKSCREEN:" at 10577.95,3362.04 h60
  text "X" at 11535.74,3362.04 h60
  text "TOP" at 11652.73,3362.04 h60
  text "BOTTOM" at 12163.73,3362.04 h60
  text "SILKSCREEN COLOR:" at 10577.95,3206.85 h60
  text "X" at 11534.74,3206.85 h60
  text "WHITE" at 11652.73,3206.85 h60
  text "OTHER" at 12163.73,3206.85 h60
  text "X" at 11662.3,3067.33 h60
  text "GREEN" at 11783.73,3063.4 h60
  text "OTHER" at 12401.73,3063.4 h60
  text "SOLDER RESIST COLOR:" at 10577.95,3056.53 h60
  text "X" at 11665.74,2909.15 h60
  text "MATTE" at 11783.73,2909.15 h60
  text "SEMI-GLOSS" at 12401.27,2908.51 h60
  text "IMMERSION GOLD (ENIG)" at 11483.73,2736.38 h60
  text "ENEPIG" at 12821.27,2729.16 h60
  text "SURFACE FINISH:" at 10422.73,2728.16 h60
  text "X" at 11305.74,2728.16 h60
  text "IMM. TIN/SILVER OR EQUIV" at 10752.27,2590.84 h60
  text "OTHER" at 12183.73,2586.9 h60
  text "ARRAY/PANEL:" at 10422.73,2431.53 h60
  text "CUT AND TRIM PER M1 BOARD OUTLINE" at 11483.73,2423.3 h60
  text "N.C. ROUTE" at 11483.73,2287.34 h60
  text "V. SCORE" at 12349.73,2287.34 h60
  text "X" at 12166.92,2285.76 h60
  text "CERTIFICATION:" at 10422.73,2158.21 h60
  text "MATERIALS AND WORKMANSHIP FOR ALL PCBS" at 11147.73,2158.21 h60
  text "TO MEET OR EXCEED THE REQUIREMENTS OF:" at 11147.73,2064.15 h60
  text "X" at 10785.24,1935.52 h60
  text "ANSI IPC-A-600F CLASS ->" at 10913.23,1935.52 h60
  text "X" at 12561.24,1935.52 h60
  text "2" at 12671.23,1935.52 h60
  text "1" at 12356.23,1934.02 h60
  text "3" at 13025.23,1934.02 h60
  text "X" at 11597.24,1787.83 h60
  text "RoHS" at 11725.23,1787.83 h60
  text "OTHER" at 12369.64,1787.83 h60
  text "PER ORDER" at 12766.69,1787.83 h60
  text "ALL BOARDS MUST MEET OR EXCEED UL94-V0 REQUIREMENTS." at 10450.27,1634.01 h60
  text "PCB MUST BEAR THE UL94V-0 UL REGISTERED MATERIAL ID NUMBER" at 10450.27,1517.94 h60
  text "ADDITIONAL REQUIREMENTS:" at 10422.73,1348.52 h60
  text "MICROSECTION:" at 10497.5,1241.39 h60
  text "YES" at 11403.23,1241.39 h60
  text "REQUIRED" at 12264.73,1097.06 h60
  text "BARE BOARD ELEC. TEST:" at 10497.5,1094.2 h60
  text "NONE" at 11803.23,1094.2 h60
  text "X" at 12146.74,1094.2 h60
  text "PER ORDER" at 12856.73,1094.2 h60
  text "XX MIL VIAS REQUIRE NON-CONDUCTIVE FILL AND PLANARIZE" at 10665.65,889.26 h59
  text "XX MIL VIAS REQUIRE CONDUCTIVE FILL AND PLANARIZE" at 10673.65,785.28 h60
  text "FAB NOTES:" at 4448.61,721.93 h60
  text "OUTER XX MIL VIAS REQUIRE 50 OHM SINGLE-ENDED IMPEDANCE" at 10672.66,621.89 h58
  text "1. THE SOLDER MASK IMAGES THAT ARE THE SAME SIZE AS THE COMPONENT PADS MAY BE ENLARGED AS PER THE" at 4460.55,573.79 h60
  text "LAYER 2 & 3 (INNER LAYERS) XX MIL WIDE, XX MIL SPACE" at 10672.78,466.96 h60
  text "MANUFACTURING CAPABILITIES BUT NOT BEYOND 0.08MM PER SIDE OR 0.15MM OVERALL." at 4621.89,440.18 h60
  text "ALL OTHER SOLDER MASK IMAGES SHALL NOT BE MODIFIED." at 4621.89,306.58 h60
  text ".Layer_Name" at -347.23,-1364.06 h60
M11 Gerber Information:
  lines w10: -1216.23,-1435.73 5383.77,-1435.73 ; -1216.23,-1232.4 5385.77,-1232.4 ; -1216.23,-1029.06 -1216.23,-1639.06 2788.77,-1639.06 5385.77,-1639.06 5385.77,-1029.06 -1215.73,-1029.06 -1215.73,-1639.06 359.77,-1639.06 ; 1248.77,-1639.06 1248.77,-1029.06 ; 2515.77,-1232.4 2515.77,-1029.06 ; 3355.77,-1232.4 3355.77,-1029.06 ; 3977.77,-1645.56 3977.77,-1442.73
  text "ALL ARTWORK VIEWED FROM TOP SIDE" at -1152.73,-1161.23 h60
  text "BOARD #:" at 1323.77,-1161.23 h60
  text ".PRJ_Number" at 1869.27,-1161.23 h60
  text "REV:" at 2713.77,-1161.23 h60
  text ".PCB_Rev" at 3005.27,-1161.23 h60
  text "SVN REV:" at 3551.77,-1161.23 h60
  text ".VersionControl_RevNumber" at 4057.77,-1161.23 h60
  text "LAYER NAME =" at -1152.73,-1364.06 h60
  text "TID #:" at 1323.77,-1364.56 h60
  text ".TID" at 1869.27,-1364.56 h60
  text "PLOT NAME =" at -1152.73,-1569.9 h60
  text ".plot_File_Name" at -347.23,-1569.9 h60
  text "GENERATED    :" at 1325.77,-1569.9 h60
  text ".Print_Date" at 2195.27,-1569.9 h60
  text ".Print_Time" at 2924.27,-1569.9 h60
  text "TEXAS INSTRUMENTS" at 4188.77,-1569.9 h60
M12 Stackup:
  drawing of 292 lines, arcs and shapes, not listed
  text "STACKUP TABLE:" at 4333.14,4323.01 h80
  text "Layer" at 4399.56,4151.37 h60
  text "Name" at 4809.47,4151.37 h60
  text "Material" at 5669.24,4151.37 h60
  text "Thickness" at 6529.01,4151.37 h60
  text "Constant" at 7178.84,4151.37 h60
  text "Board Layer Stack" at 7748.7,4151.37 h60
  text "Board Layer Stack" at 8868.39,4151.37 h60
  text "1" at 4399.56,4031.37 h60
  text "Top Overlay" at 4809.47,4031.37 h60
  text "2" at 4399.56,3911.37 h60
  text "Top Solder" at 4809.47,3911.37 h60
  text "Solder Resist" at 5669.24,3911.37 h60
  text "0.40mil" at 6529.01,3911.37 h60
  text "3.5" at 7178.84,3911.37 h60
  text "3" at 4399.56,3791.37 h60
  text "Top Layer" at 4809.47,3791.37 h60
  text "Copper" at 5669.24,3791.37 h60
  text "2.10mil" at 6529.01,3791.37 h60
  text "4" at 4399.56,3671.37 h60
  text "Dielectric1" at 4809.47,3671.37 h60
  text "FR-4 High Tg" at 5669.24,3671.37 h60
  text "57.00mil" at 6529.01,3671.37 h60
  text "4.8" at 7178.84,3671.37 h60
  text "5" at 4399.56,3551.37 h60
  text "Bottom Layer" at 4809.47,3551.37 h60
  text "Copper" at 5669.24,3551.37 h60
  text "2.10mil" at 6529.01,3551.37 h60
  text "6" at 4399.56,3431.37 h60
  text "Bottom Solder" at 4809.47,3431.37 h60
  text "Solder Resist" at 5669.24,3431.37 h60
  text "0.40mil" at 6529.01,3431.37 h60
  text "3.5" at 7178.84,3431.37 h60
  text ".Layer_Name" at -347.23,-1364.06 h60
M13 Component Bodies Top:
  text ".Layer_Name" at -347.23,-1364.06 h60
M14 Component Bodies Bottom:
  text ".Layer_Name" at -347.23,-1364.06 h60
M15 Courtyards Top:
  text ".Layer_Name" at -347.23,-1364.06 h60
M16 Courtyards Bottom:
  text ".Layer_Name" at -347.23,-1364.06 h60
Drill Drawing:
  circle w10: c4432.53,2819.93 r33.33
  lines w10: 4399.19,2053.26 4415.86,2053.26 4432.53,2036.6 4449.19,2053.26 4465.86,2053.26 4449.19,2069.93 4465.86,2086.6 4449.19,2086.6 4432.53,2103.26 4415.86,2086.6 4399.19,2086.6 4415.86,2069.93 4399.19,2053.26 ; 4399.19,2186.6 4465.86,2186.6 4465.86,2253.26 4399.19,2253.26 4399.19,2186.6 ; 4399.19,2636.6 4432.53,2653.26 4465.86,2636.6 4449.19,2669.93 4465.86,2703.26 4432.53,2686.6 4399.19,2703.26 4415.86,2669.93 4399.19,2636.6 ; 4399.19,2953.26 4415.86,2953.26 4415.86,2936.6 4449.19,2936.6 4449.19,2953.26 4465.86,2953.26 4465.86,2986.6 4449.19,2986.6 4449.19,3003.26 4415.86,3003.26 4415.86,2986.6 4399.19,2986.6 4399.19,2953.26
  lines w15: 4339.4,1991.6 9598,1991.6 ; 4339.4,3191.6 9598,3191.6 ; 4890.28,1841.6 4890.28,3341.6 ; 5480.12,1841.6 5480.12,3341.6 ; 6629.78,1841.6 6629.78,3341.6 ; 7135.66,1841.6 7135.66,3341.6 ; 7869.46,1841.6 7869.46,3341.6 ; 8975.14,1841.6 8975.14,3341.6 ; 4339.4,1841.6 9598,1841.6 9598,3341.6 4339.4,3341.6 4339.4,1841.6
  text "Symbol" at 4429.4,3236.6 h72
  text "Count" at 4935.28,3236.6 h72
  text "Hole Size" at 5525.12,3236.6 h72
  text "Plated" at 6674.78,3236.6 h72
  text "Hole Type" at 7180.66,3236.6 h72
  text "Tolerance(Mils)" at 7914.46,3236.6 h72
  text "Tenting" at 9020.14,3236.6 h72
  text "59" at 4935.28,3086.6 h60
  text "12.00mil (0.305mm)" at 5525.12,3086.6 h60
  text "PTH" at 6674.78,3086.6 h60
  text "Round" at 7180.66,3086.6 h60
  text "+0/-12" at 7914.46,3086.6 h60
  text "Both" at 9020.14,3086.6 h60
  text "A" at 4400.31,3076.61 h66.67
  text "DRILL TABLE:" at 4340.14,2985.36 h80
  text "50" at 4935.28,2936.6 h60
  text "10.00mil (0.254mm)" at 5525.12,2936.6 h60
  text "PTH" at 6674.78,2936.6 h60
  text "Round" at 7180.66,2936.6 h60
  text "8" at 4935.28,2786.6 h60
  text "35.43mil (0.900mm)" at 5525.12,2786.6 h60
  text "PTH" at 6674.78,2786.6 h60
  text "Round" at 7180.66,2786.6 h60
  text "6" at 4935.28,2636.6 h60
  text "20.00mil (0.508mm)" at 5525.12,2636.6 h60
  text "PTH" at 6674.78,2636.6 h60
  text "Round" at 7180.66,2636.6 h60
  text "4" at 4935.28,2486.6 h60
  text "125.98mil (3.200mm)" at 5525.12,2486.6 h60
  text "PTH" at 6674.78,2486.6 h60
  text "Round" at 7180.66,2486.6 h60
  text "+/-3" at 7914.46,2486.6 h60
  text "D" at 4400.31,2476.61 h66.67
  text "3" at 4935.28,2336.6 h60
  text "214.57mil (5.450mm)" at 5525.12,2336.6 h60
  text "PTH" at 6674.78,2336.6 h60
  text "Round" at 7180.66,2336.6 h60
  text "+/-3" at 7914.46,2336.6 h60
  text "E" at 4400.31,2326.61 h66.67
  text "2" at 4935.28,2186.6 h60
  text "40.00mil (1.016mm)" at 5525.12,2186.6 h60
  text "PTH" at 6674.78,2186.6 h60
  text "Round" at 7180.66,2186.6 h60
  text "2" at 4935.28,2036.6 h60
  text "51.18mil (1.300mm)" at 5525.12,2036.6 h60
  text "PTH" at 6674.78,2036.6 h60
  text "Round" at 7180.66,2036.6 h60
  text "134 Total" at 4935.28,1886.6 h60
  text ".Layer_Name" at -347.23,-1364.06 h60
M17 Embedded Cavity:
  text ".Layer_Name" at -347.23,-1364.06 h60
M18 Embedded Assembly:
  text ".Layer_Name" at -347.23,-1364.06 h60
M19 Embedded Keepout:
  text ".Layer_Name" at -347.23,-1364.06 h60

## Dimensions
175,175 to 0,0 on M2 Board Dimensions
175,175 to 0,0 on M2 Board Dimensions
175,175 to 0,2100 on M2 Board Dimensions
175,175 to 3125,0 on M2 Board Dimensions
-924.23,-905.56 to 75.77,-905.56 on M2 Board Dimensions
146.6,144.82 to -137.94,-75.25 on M2 Board Dimensions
